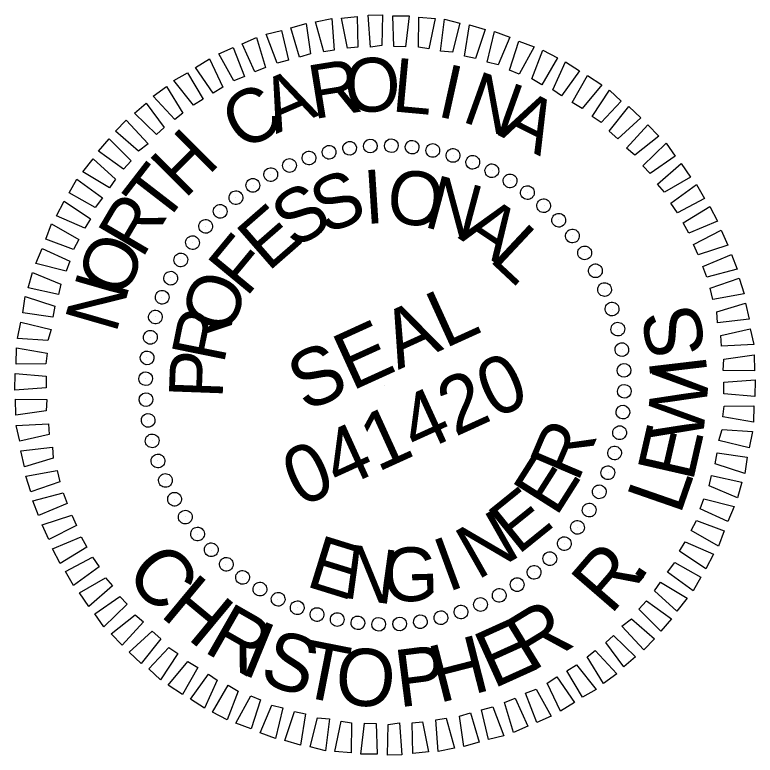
# Model space of a CAD drawing. Extents: x 2247864 to 2249896, y 662531 to 664296.
# Drawn here: x 2249747.5 to 2249825, y 664218.1 to 664295.6 of the extents above; entities that cross this region are included whole.
import ezdxf

# ---------------------------------------------------------------- set-up
doc = ezdxf.new("R2010")
doc.units = 0
doc.layers.add('Sheet PE Seal Cell', color=7, linetype='Continuous')

msp = doc.modelspace()

# ---------------------------------------------------------------- linework, layer by layer
at = {"layer": 'Sheet PE Seal Cell'}
for p, q in [((2249782.507, 664281.685), (2249782.507, 664281.685)), ((2249784.708, 664281.919), (2249784.708, 664281.919)), ((2249786.901, 664281.93), (2249786.901, 664281.93)), ((2249789.09, 664281.828), (2249789.09, 664281.828)), ((2249791.247, 664281.437), (2249791.247, 664281.437)), ((2249778.308, 664280.651), (2249778.308, 664280.651)), ((2249780.409, 664281.224), (2249780.409, 664281.224)), ((2249793.399, 664280.934), (2249793.399, 664280.934)), ((2249776.244, 664279.875), (2249776.244, 664279.875)), ((2249795.431, 664280.212), (2249795.431, 664280.212)), ((2249797.481, 664279.333), (2249797.481, 664279.333)), ((2249774.262, 664278.918), (2249774.262, 664278.918)), ((2249799.344, 664278.258), (2249799.344, 664278.258)), ((2249772.43, 664277.753), (2249772.43, 664277.753)), ((2249801.178, 664277.006), (2249801.178, 664277.006)), ((2249770.594, 664276.477), (2249770.594, 664276.477)), ((2249768.932, 664275.06), (2249768.932, 664275.06)), ((2249802.897, 664275.647), (2249802.897, 664275.647)), ((2249767.444, 664273.503), (2249767.444, 664273.503)), ((2249804.454, 664274.158), (2249804.454, 664274.158)), ((2249805.871, 664272.496), (2249805.871, 664272.496)), ((2249766.084, 664271.784), (2249766.084, 664271.784)), ((2249807.147, 664270.66), (2249807.147, 664270.66)), ((2249764.832, 664269.95), (2249764.832, 664269.95)), ((2249763.758, 664268.087), (2249763.758, 664268.087)), ((2249808.311, 664268.828), (2249808.311, 664268.828)), ((2249809.269, 664266.847), (2249809.269, 664266.847)), ((2249762.878, 664266.038), (2249762.878, 664266.038)), ((2249810.045, 664264.783), (2249810.045, 664264.783)), ((2249762.156, 664264.005), (2249762.156, 664264.005)), ((2249810.618, 664262.681), (2249810.618, 664262.681)), ((2249761.653, 664261.853), (2249761.653, 664261.853)), ((2249811.079, 664260.584), (2249811.079, 664260.584)), ((2249761.262, 664259.697), (2249761.262, 664259.697)), ((2249811.313, 664258.382), (2249811.313, 664258.382)), ((2249761.161, 664257.508), (2249761.161, 664257.508)), ((2249786.242, 664256.848), (2249786.242, 664256.848)), ((2249811.323, 664256.189), (2249811.323, 664256.189)), ((2249761.171, 664255.314), (2249761.171, 664255.314)), ((2249811.222, 664254), (2249811.222, 664254)), ((2249761.405, 664253.113), (2249761.405, 664253.113)), ((2249810.831, 664251.844), (2249810.831, 664251.844)), ((2249761.866, 664251.016), (2249761.866, 664251.016)), ((2249810.328, 664249.692), (2249810.328, 664249.692)), ((2249762.439, 664248.914), (2249762.439, 664248.914)), ((2249809.606, 664247.659), (2249809.606, 664247.659)), ((2249763.215, 664246.85), (2249763.215, 664246.85)), ((2249808.726, 664245.61), (2249808.726, 664245.61)), ((2249764.173, 664244.869), (2249764.173, 664244.869)), ((2249807.652, 664243.747), (2249807.652, 664243.747)), ((2249765.337, 664243.037), (2249765.337, 664243.037)), ((2249806.4, 664241.913), (2249806.4, 664241.913)), ((2249766.614, 664241.201), (2249766.614, 664241.201)), ((2249805.04, 664240.194), (2249805.04, 664240.194)), ((2249768.03, 664239.538), (2249768.03, 664239.538)), ((2249803.552, 664238.637), (2249803.552, 664238.637)), ((2249769.588, 664238.05), (2249769.588, 664238.05)), ((2249801.89, 664237.22), (2249801.89, 664237.22)), ((2249771.306, 664236.69), (2249771.306, 664236.69)), ((2249800.054, 664235.944), (2249800.054, 664235.944)), ((2249773.141, 664235.438), (2249773.141, 664235.438)), ((2249798.222, 664234.779), (2249798.222, 664234.779)), ((2249775.004, 664234.364), (2249775.004, 664234.364)), ((2249777.053, 664233.485), (2249777.053, 664233.485)), ((2249796.241, 664233.821), (2249796.241, 664233.821)), ((2249779.085, 664232.762), (2249779.085, 664232.762)), ((2249792.075, 664232.473), (2249792.075, 664232.473)), ((2249794.176, 664233.046), (2249794.176, 664233.046)), ((2249781.238, 664232.26), (2249781.238, 664232.26)), ((2249783.394, 664231.869), (2249783.394, 664231.869)), ((2249785.583, 664231.767), (2249785.583, 664231.767)), ((2249787.776, 664231.777), (2249787.776, 664231.777)), ((2249789.977, 664232.011), (2249789.977, 664232.011))]:
    msp.add_line(p, q, dxfattribs=at)
for points in [[(2249779.849, 664291.738), (2249778.956, 664294.903), (2249780.669, 664295.244), (2249780.908, 664291.946)], [(2249782.303, 664292.142), (2249781.7, 664295.274), (2249783.317, 664295.462), (2249783.403, 664292.259)], [(2249784.723, 664292.256), (2249784.463, 664295.599), (2249785.986, 664295.634), (2249785.915, 664292.414)], [(2249787.165, 664292.325), (2249787.079, 664295.527), (2249788.78, 664295.533), (2249788.394, 664292.28)], [(2249789.734, 664292.232), (2249789.781, 664295.385), (2249791.498, 664295.234), (2249790.848, 664292.08)], [(2249777.301, 664291.181), (2249776.383, 664294.28), (2249777.988, 664294.737), (2249778.455, 664291.543)], [(2249792.069, 664291.812), (2249792.459, 664295.177), (2249794.077, 664294.76), (2249793.318, 664291.722)], [(2249794.556, 664291.297), (2249795.099, 664294.567), (2249796.738, 664294.105), (2249795.711, 664291.054)], [(2249774.951, 664290.55), (2249773.785, 664293.591), (2249775.411, 664294.002), (2249776.126, 664290.866)], [(2249796.928, 664290.674), (2249797.715, 664293.89), (2249799.305, 664293.296), (2249798.103, 664290.386)], [(2249772.614, 664289.65), (2249771.266, 664292.608), (2249772.788, 664293.246), (2249773.726, 664290.102)], [(2249770.409, 664288.7), (2249768.834, 664291.554), (2249770.356, 664292.193), (2249771.522, 664289.153)], [(2249799.291, 664289.828), (2249800.273, 664292.858), (2249801.863, 664292.264), (2249800.306, 664289.411)], [(2249801.63, 664288.916), (2249802.79, 664291.917), (2249804.305, 664291.124), (2249802.682, 664288.296)], [(2249768.238, 664287.436), (2249766.41, 664290.12), (2249767.874, 664291.007), (2249769.267, 664288.07)], [(2249803.804, 664287.764), (2249805.162, 664290.69), (2249806.628, 664289.765), (2249804.744, 664287.148)], [(2249766.178, 664286.168), (2249764.123, 664288.748), (2249765.563, 664289.569), (2249767.208, 664286.802)], [(2249805.837, 664286.437), (2249807.46, 664289.265), (2249808.947, 664288.294), (2249806.888, 664285.817)], [(2249764.222, 664284.672), (2249761.961, 664287.103), (2249763.362, 664288.127), (2249765.074, 664285.335)], [(2249807.932, 664284.974), (2249809.754, 664287.728), (2249810.988, 664286.587), (2249808.872, 664284.359)], [(2249762.308, 664283.086), (2249760.017, 664285.339), (2249761.241, 664286.391), (2249763.118, 664283.84)], [(2249809.733, 664283.433), (2249811.796, 664286.021), (2249813.051, 664284.834), (2249810.645, 664282.639)], [(2249760.41, 664281.342), (2249758.025, 664283.442), (2249759.141, 664284.61), (2249761.423, 664282.133)], [(2249811.527, 664281.667), (2249813.763, 664284.115), (2249814.907, 664282.933), (2249812.417, 664280.919)], [(2249758.844, 664279.474), (2249756.227, 664281.359), (2249757.347, 664282.638), (2249759.658, 664280.34)], [(2249813.25, 664279.815), (2249815.685, 664282.188), (2249816.642, 664280.811), (2249814.004, 664279.005)], [(2249757.385, 664277.491), (2249754.582, 664279.18), (2249755.66, 664280.551), (2249758, 664278.431)], [(2249814.791, 664277.88), (2249817.264, 664280.051), (2249818.242, 664278.628), (2249815.5, 664277.049)], [(2249755.901, 664275.441), (2249753.16, 664276.994), (2249753.949, 664278.398), (2249756.653, 664276.443)], [(2249816.196, 664275.883), (2249818.863, 664277.867), (2249819.705, 664276.382), (2249816.876, 664274.874)], [(2249754.794, 664273.288), (2249751.842, 664274.581), (2249752.636, 664276.096), (2249755.389, 664274.274)], [(2249817.464, 664273.823), (2249820.256, 664275.535), (2249821.052, 664274.029), (2249818.053, 664272.773)], [(2249753.617, 664271.048), (2249750.703, 664272.138), (2249751.297, 664273.728), (2249754.191, 664272.079)], [(2249818.546, 664271.569), (2249821.441, 664273.053), (2249822.146, 664271.506), (2249819.044, 664270.477)], [(2249752.841, 664268.772), (2249749.671, 664269.58), (2249750.331, 664271.145), (2249753.237, 664269.831)], [(2249819.537, 664269.273), (2249822.536, 664270.53), (2249823.129, 664268.987), (2249819.944, 664268.14)], [(2249752.036, 664266.317), (2249748.862, 664267.013), (2249749.324, 664268.652), (2249752.3, 664267.426)], [(2249820.305, 664266.986), (2249823.341, 664268.039), (2249823.864, 664266.41), (2249820.575, 664265.79)], [(2249751.459, 664263.966), (2249748.298, 664264.393), (2249748.561, 664266.107), (2249751.657, 664265.1)], [(2249820.999, 664264.499), (2249823.985, 664265.421), (2249824.372, 664263.729), (2249821.07, 664263.378)], [(2249750.924, 664261.524), (2249747.754, 664261.728), (2249748.083, 664263.417), (2249751.279, 664262.675)], [(2249821.402, 664262.046), (2249824.493, 664262.74), (2249824.858, 664261.093), (2249821.474, 664260.924)], [(2249750.723, 664259.07), (2249747.612, 664259.026), (2249747.651, 664260.747), (2249750.875, 664260.183)], [(2249821.715, 664259.551), (2249824.909, 664260.017), (2249824.96, 664258.337), (2249821.65, 664258.367)], [(2249750.767, 664256.563), (2249747.469, 664256.324), (2249747.509, 664258.045), (2249750.766, 664257.771)], [(2249821.717, 664257.134), (2249825.015, 664257.373), (2249824.975, 664255.652), (2249821.718, 664255.926)], [(2249750.769, 664254.146), (2249747.575, 664253.679), (2249747.524, 664255.359), (2249750.834, 664255.329)], [(2249821.761, 664254.627), (2249824.873, 664254.671), (2249824.833, 664252.949), (2249821.609, 664253.513)], [(2249751.082, 664251.651), (2249747.992, 664250.957), (2249747.626, 664252.604), (2249751.011, 664252.772)], [(2249821.56, 664252.173), (2249824.73, 664251.969), (2249824.401, 664250.28), (2249821.206, 664251.022)], [(2249751.486, 664249.197), (2249748.499, 664248.276), (2249748.112, 664249.968), (2249751.414, 664250.319)], [(2249821.025, 664249.731), (2249824.187, 664249.303), (2249823.923, 664247.59), (2249820.827, 664248.597)], [(2249752.179, 664246.711), (2249749.143, 664245.657), (2249748.62, 664247.287), (2249751.909, 664247.907)], [(2249820.448, 664247.38), (2249823.622, 664246.683), (2249823.16, 664245.044), (2249820.184, 664246.27)], [(2249752.947, 664244.424), (2249749.948, 664243.167), (2249749.355, 664244.71), (2249752.54, 664245.557)], [(2249819.643, 664244.925), (2249822.814, 664244.117), (2249822.153, 664242.552), (2249819.247, 664243.865)], [(2249753.938, 664242.128), (2249751.043, 664240.644), (2249750.338, 664242.191), (2249753.44, 664243.22)], [(2249818.867, 664242.648), (2249821.782, 664241.559), (2249821.187, 664239.969), (2249818.293, 664241.618)], [(2249755.02, 664239.874), (2249752.229, 664238.162), (2249751.433, 664239.668), (2249754.432, 664240.924)], [(2249817.69, 664240.409), (2249820.642, 664239.116), (2249819.849, 664237.601), (2249817.095, 664239.423)], [(2249756.288, 664237.814), (2249753.621, 664235.83), (2249752.78, 664237.314), (2249755.609, 664238.823)], [(2249816.583, 664238.256), (2249819.324, 664236.702), (2249818.535, 664235.299), (2249815.831, 664237.254)], [(2249757.693, 664235.817), (2249755.22, 664233.646), (2249754.243, 664235.069), (2249756.985, 664236.648)], [(2249815.099, 664236.206), (2249817.903, 664234.516), (2249816.824, 664233.146), (2249814.484, 664235.266)], [(2249759.234, 664233.882), (2249756.799, 664231.508), (2249755.842, 664232.885), (2249758.48, 664234.692)], [(2249813.641, 664234.223), (2249816.258, 664232.338), (2249815.137, 664231.058), (2249812.826, 664233.357)], [(2249760.957, 664232.029), (2249758.721, 664229.582), (2249757.578, 664230.764), (2249760.067, 664232.778)], [(2249812.074, 664232.355), (2249814.46, 664230.255), (2249813.343, 664229.087), (2249811.061, 664231.564)], [(2249762.751, 664230.264), (2249760.688, 664227.676), (2249759.433, 664228.862), (2249761.84, 664231.058)], [(2249810.176, 664230.611), (2249812.467, 664228.358), (2249811.243, 664227.306), (2249809.366, 664229.857)], [(2249764.552, 664228.722), (2249762.73, 664225.969), (2249761.496, 664227.11), (2249763.612, 664229.338)], [(2249808.262, 664229.024), (2249810.524, 664226.593), (2249809.122, 664225.57), (2249807.41, 664228.361)], [(2249766.647, 664227.26), (2249765.024, 664224.432), (2249763.537, 664225.403), (2249765.596, 664227.879)], [(2249806.306, 664227.529), (2249808.361, 664224.948), (2249806.922, 664224.128), (2249805.276, 664226.895)], [(2249768.68, 664225.933), (2249767.322, 664223.006), (2249765.856, 664223.932), (2249767.741, 664226.549)], [(2249804.247, 664226.26), (2249806.074, 664223.577), (2249804.61, 664222.69), (2249803.217, 664225.626)], [(2249770.854, 664224.781), (2249769.694, 664221.78), (2249768.179, 664222.573), (2249769.802, 664225.4)], [(2249802.075, 664224.996), (2249803.65, 664222.143), (2249802.128, 664221.504), (2249800.963, 664224.544)], [(2249773.193, 664223.868), (2249772.211, 664220.838), (2249770.621, 664221.433), (2249772.179, 664224.285)], [(2249799.871, 664224.047), (2249801.218, 664221.089), (2249799.696, 664220.451), (2249798.758, 664223.595)], [(2249775.556, 664223.022), (2249774.769, 664219.806), (2249773.18, 664220.401), (2249774.381, 664223.311)], [(2249797.533, 664223.146), (2249798.699, 664220.106), (2249797.073, 664219.695), (2249796.359, 664222.831)], [(2249777.928, 664222.4), (2249777.385, 664219.13), (2249775.746, 664219.592), (2249776.773, 664222.643)], [(2249795.184, 664222.515), (2249796.101, 664219.417), (2249794.496, 664218.96), (2249794.029, 664222.154)], [(2249780.416, 664221.885), (2249780.026, 664218.52), (2249778.407, 664218.937), (2249779.166, 664221.975)], [(2249782.75, 664221.465), (2249782.703, 664218.312), (2249780.986, 664218.463), (2249781.637, 664221.617)], [(2249790.182, 664221.555), (2249790.785, 664218.423), (2249789.167, 664218.235), (2249789.081, 664221.438)], [(2249792.635, 664221.958), (2249793.528, 664218.794), (2249791.815, 664218.453), (2249791.576, 664221.75)], [(2249785.32, 664221.372), (2249785.405, 664218.169), (2249783.705, 664218.164), (2249784.091, 664221.417)], [(2249787.761, 664221.441), (2249788.021, 664218.097), (2249786.498, 664218.063), (2249786.569, 664221.282)]]:
    msp.add_lwpolyline(points, close=True, dxfattribs=at)
for centre, major_axis in [((2249782.536, 664281.653), (-0.106, 0.712)), ((2249784.712, 664281.882), (-0.044, 0.719)), ((2249786.9, 664281.92), (0.019, 0.72)), ((2249789.082, 664281.767), (0.082, 0.715)), ((2249791.243, 664281.425), (0.144, 0.706)), ((2249778.285, 664280.633), (-0.228, 0.683)), ((2249780.388, 664281.236), (-0.168, 0.7)), ((2249793.366, 664280.895), (0.205, 0.69)), ((2249776.242, 664279.849), (-0.287, 0.66)), ((2249795.435, 664280.183), (0.264, 0.67)), ((2249774.276, 664278.89), (-0.344, 0.633)), ((2249797.434, 664279.293), (0.321, 0.644)), ((2249799.347, 664278.232), (0.376, 0.614)), ((2249772.4, 664277.763), (-0.397, 0.6)), ((2249801.161, 664277.009), (0.428, 0.579)), ((2249770.63, 664276.477), (-0.448, 0.563)), ((2249768.979, 664275.041), (-0.496, 0.522)), ((2249802.861, 664275.632), (0.477, 0.539)), ((2249804.435, 664274.112), (0.522, 0.496)), ((2249767.459, 664273.468), (-0.539, 0.477)), ((2249805.87, 664272.46), (0.563, 0.448)), ((2249766.082, 664271.767), (-0.579, 0.428)), ((2249807.156, 664270.69), (0.6, 0.397)), ((2249764.858, 664269.953), (-0.614, 0.376)), ((2249808.283, 664268.815), (0.633, 0.344)), ((2249763.798, 664268.04), (-0.644, 0.321)), ((2249809.242, 664266.848), (0.66, 0.287)), ((2249762.908, 664266.041), (-0.67, 0.264)), ((2249810.026, 664264.806), (0.683, 0.228)), ((2249762.195, 664263.972), (-0.69, 0.205)), ((2249810.629, 664262.702), (0.7, 0.168)), ((2249761.666, 664261.849), (-0.706, 0.144)), ((2249811.047, 664260.555), (0.712, 0.106)), ((2249761.323, 664259.688), (-0.715, 0.082)), ((2249811.275, 664258.379), (0.719, 0.044)), ((2249761.171, 664257.506), (-0.72, 0.019)), ((2249811.313, 664256.191), (0.72, -0.019)), ((2249761.209, 664255.318), (-0.719, -0.044)), ((2249811.161, 664254.008), (0.715, -0.082)), ((2249761.437, 664253.142), (-0.712, -0.106)), ((2249810.818, 664251.847), (0.706, -0.144)), ((2249761.855, 664250.994), (-0.7, -0.168)), ((2249810.289, 664249.724), (0.69, -0.205)), ((2249762.458, 664248.891), (-0.683, -0.228)), ((2249809.577, 664247.656), (0.67, -0.264)), ((2249763.242, 664246.849), (-0.66, -0.287)), ((2249808.687, 664245.657), (0.644, -0.321)), ((2249764.201, 664244.882), (-0.633, -0.344)), ((2249807.626, 664243.743), (0.614, -0.376)), ((2249765.328, 664243.007), (-0.6, -0.397)), ((2249806.402, 664241.929), (0.579, -0.428)), ((2249766.614, 664241.236), (-0.563, -0.448)), ((2249805.025, 664240.229), (0.539, -0.477)), ((2249768.049, 664239.585), (-0.522, -0.496)), ((2249803.505, 664238.655), (0.496, -0.522)), ((2249769.623, 664238.065), (-0.477, -0.539)), ((2249801.854, 664237.22), (0.448, -0.563)), ((2249771.323, 664236.688), (-0.428, -0.579)), ((2249773.137, 664235.465), (-0.376, -0.614)), ((2249800.084, 664235.934), (0.397, -0.6)), ((2249798.208, 664234.807), (0.344, -0.633)), ((2249775.051, 664234.404), (-0.321, -0.644)), ((2249777.049, 664233.514), (-0.264, -0.67)), ((2249796.242, 664233.848), (0.287, -0.66)), ((2249779.118, 664232.801), (-0.205, -0.69)), ((2249792.096, 664232.461), (0.168, -0.7)), ((2249794.199, 664233.064), (0.228, -0.683)), ((2249781.241, 664232.272), (-0.144, -0.706)), ((2249783.402, 664231.93), (-0.082, -0.715)), ((2249785.585, 664231.777), (-0.019, -0.72)), ((2249787.772, 664231.815), (0.044, -0.719)), ((2249789.948, 664232.044), (0.106, -0.712))]:
    msp.add_ellipse(centre, major_axis=major_axis, ratio=0.999708, dxfattribs=at)

# ---------------------------------------------------------------- texts
for s, height, rotation, p in [('R', 5.638, 9.11904, (2249778.722, 664284.686)), ('O', 5.638, 1.91911, (2249782.081, 664285.393)), ('L', 5.638, 354.71882, (2249786.852, 664285.534)), ('I', 5.638, 347.51808, (2249791.533, 664285.029)), ('A', 5.638, 23.51826, (2249774.817, 664283.127)), ('N', 5.639, 340.31685, (2249794.132, 664284.51)), ('C', 5.638, 30.71781, (2249771.347, 664281.216)), ('A', 5.639, 333.1151, (2249798.04, 664283.049)), ('H', 5.638, 45.11742, (2249765.261, 664276.244)), ('T', 5.638, 52.31772, (2249762.987, 664273.395)), ('S', 5.638, 22.39834, (2249779.962, 664272.559)), ('I', 5.638, 3.68755, (2249784.165, 664273.705)), ('O', 5.638, 354.33143, (2249786.276, 664273.897)), ('N', 5.638, 344.97455, (2249790.153, 664273.466)), ('S', 5.638, 31.75355, (2249776.707, 664271.02)), ('R', 5.639, 59.51845, (2249760.806, 664269.983)), ('E', 5.638, 41.10901, (2249774.003, 664268.634)), ('A', 5.639, 326.25821, (2249793.825, 664272.282)), ('L', 5.639, 316.89879, (2249797.03, 664269.951)), ('F', 5.638, 50.46498, (2249771.713, 664265.942)), ('O', 5.639, 66.71968, (2249758.952, 664265.732)), ('N', 5.639, 73.92144, (2249758.061, 664262.139)), ('O', 5.639, 69.17918, (2249769.934, 664261.89)), ('SEAL', 5.9982, 24.49794, (2249777.883, 664253.972)), ('S', 5.998, 100.55241, (2249819.889, 664260.25)), ('R', 5.639, 78.53759, (2249769.357, 664258.935)), ('P', 5.639, 87.89683, (2249769.228, 664255.359)), ('041420', 5.9982, 24.49794, (2249777.333, 664243.988)), ('I', 5.998, 96.75046, (2249820.04, 664258.011)), ('W', 5.998, 84.21639, (2249819.487, 664250.649)), ('R', 5.639, 66.97935, (2249806.433, 664246.543)), ('E', 5.998, 77.10705, (2249818.464, 664246.582)), ('E', 5.638, 57.62203, (2249804.177, 664242.933)), ('L', 5.998, 70.83229, (2249817.149, 664243.122)), ('E', 5.638, 38.9097, (2249800.163, 664238.96)), ('N', 5.638, 29.55433, (2249795.907, 664236.362)), ('E', 5.638, 342.77483, (2249777.808, 664235.807)), ('I', 5.638, 20.19914, (2249792.797, 664235.109)), ('C', 5.998, 310.69992, (2249758.855, 664237.009)), ('N', 5.639, 352.1319, (2249781.657, 664234.594)), ('G', 5.638, 1.48818, (2249786.048, 664234.122)), ('R', 5.998, 49.11789, (2249809.877, 664232.661)), ('.', 5.998, 56.59815, (2249812.825, 664235.943)), ('H', 5.998, 320.28207, (2249762.54, 664232.727)), ('R', 5.998, 330.26605, (2249767.081, 664228.983)), ('R', 5.998, 31.43728, (2249801.415, 664226.625)), ('E', 5.998, 24.32794, (2249797.558, 664224.979)), ('I', 5.998, 337.74631, (2249770.871, 664226.725)), ('S', 5.998, 341.54826, (2249772.903, 664225.772)), ('T', 5.998, 348.87397, (2249776.974, 664224.325)), ('H', 5.998, 14.34395, (2249791.861, 664223.5)), ('O', 5.998, 355.67421, (2249780.89, 664223.456)), ('P', 5.998, 7.23461, (2249787.69, 664223.061))]:
    msp.add_text(s, height=height, rotation=rotation, dxfattribs=at).set_placement(p)

doc.saveas('drawing.dxf')
